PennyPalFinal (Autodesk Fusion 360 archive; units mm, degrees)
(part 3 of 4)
extrude "Extrude211" add of existing geometry blind 2.8
sketch "Sketch51" plane through (0, 0, -35) normal (0, 0, -1) x axis (1, 0, 0)
  line L1 (35, 10.0895) -> (24, 10.0895)
  line L2 (35, 24.0895) -> (35, 10.0895)
  line L3 (24, 24.0895) -> (35, 24.0895)
  line L4 (24, 10.0895) -> (24, 24.0895)
  line L5 (37, 8.0895) -> (22, 8.0895)
  line L6 (37, 26.0895) -> (37, 8.0895)
  line L7 (22, 26.0895) -> (37, 26.0895)
  line L8 (22, 8.0895) -> (22, 26.0895)
  line L9 (-24, 24.0895) -> (-35, 24.0895)
  line L10 (-24, 10.0895) -> (-35, 10.0895)
  line L11 (-24, 24.0895) -> (-24, 10.0895)
  line L12 (-35, 24.0895) -> (-24, 24.0895)
  line L13 (-35, 10.0895) -> (-35, 24.0895)
  line L14 (-22, 26.0895) -> (-37, 26.0895)
  line L15 (-22, 26.0895) -> (-22, 8.0895)
  line L16 (-22, 8.0895) -> (-37, 8.0895)
  line L17 (-37, 8.0895) -> (-37, 26.0895)
  dimension "d829" = 2
  dimension "d830" = 2
extrude "Extrude212" add sketch "Sketch51" profile of L1 L2 L3 L4 L7 L6 L8 L5 to an object
extrude "Extrude213" add sketch "Sketch51" profile of L9 L10 L11 L12 L13 L17 L15 L16 L14 to an object
extrude "Extrude214" cut sketch "Sketch51" profile of L1 L2 L3 L4 L9 L10 L11 L12 L13 against normal blind 1
offset_faces "OffsetFaces15" distance -0.2
extrude "Extrude11" cut sketch "speakerchamber" profile of C3 against normal blind 13
offset_faces "OffsetFaces1" distance -1
offset_faces "OffsetFaces2" distance 1
offset_faces "OffsetFaces16" distance -0.2
remove_body "RemoveBody34"
remove_instance "RemoveInstance1"
combine "Combine15"
extrude "Extrude215" add of existing geometry blind 1 bodies "solwall"
extrude "Extrude216" cut of existing geometry to an object
combine "Combine18"
offset_faces "OffsetFaces18" distance -0.7
extrude "Extrude3" add of existing geometry to an object
offset_faces "OffsetFaces21" distance 0.1
offset_faces "OffsetFaces22" distance -0.05
offset_faces "OffsetFaces23" distance -0.05
offset_faces "OffsetFaces24" distance -0.6
offset_faces "OffsetFaces25" distance -0.05
offset_faces "OffsetFaces26" distance -0.1
offset_faces "OffsetFaces27" distance -0.1
offset_faces "OffsetFaces29" distance -0.7
extrude "Extrude217" add of existing geometry to an object
offset_faces "OffsetFaces31" distance -0.2
sketch "Sketch52" plane through (0, 0, -55) normal (0, 0, -1) x axis (1, 0, 0)
  line L1 (-17.5, -30.7246) -> (17.5, -30.7246)
  line L2 (17.5, 30.7246) -> (-17.5, 30.7246)
  line L3 (36.3634, -30.4187) -> (34.0742, -30.4187)
  line L4 (37.5634, -30.4187) -> (36.3634, -30.4187)
  line L5 (37.5634, -39.466) -> (37.5634, -30.4187)
  line L6 (36.3634, -39.466) -> (37.5634, -39.466)
  line L7 (27.3808, -39.466) -> (36.3634, -39.466)
  line L8 (26.1808, -39.466) -> (27.3808, -39.466)
  line L9 (26.1808, -33.5357) -> (26.1808, -39.466)
  curve K1 (-20.8113, 34.4824) -> (-27.9104, 39.7996)
  curve K2 (-48.969, 26.4968) -> (-47.2168, 17.802)
  curve K3 (-47.2168, -17.802) -> (-48.969, -26.4968)
  curve K4 (-27.9104, -39.7996) -> (-20.8113, -34.4824)
  line L10 (15.2717, -34.641) -> (-17.5, -34.641)
  curve K5 (15.2717, -34.641) -> (21.515, -40.142)
  curve K6 (43.6144, -30.7496) -> (44.3437, -21.8956)
  curve K7 (44.3437, 21.8956) -> (43.6144, 30.7496)
  curve K8 (21.515, 40.142) -> (15.2717, 34.641)
  line L11 (-17.5, 34.641) -> (15.2717, 34.641)
  line L12 (0, 30) -> (0, -30.7246)
  line L13 (17.5, 28.7246) -> (-17.5, 28.7246)
  line L14 (-17.5, -28.7246) -> (17.5, -28.7246)
  line L15 (-17.5, 30.7246) -> (-17.5, -30.7246)
  line L16 (17.5, 30.7246) -> (17.5, -30.7246)
  arc A1 centre (31.8067, -32.1137) radius 11.1166 clockwise from (20.9426, -34.4695) to (20.801, -30.5467)
  arc A2 centre (17.5, 0) radius 30.7246 clockwise from (20.801, -30.5467) to (17.5, -30.7246)
  arc A3 centre (-17.5, 0) radius 30.7246 clockwise from (-17.5, -30.7246) to (-17.5, 30.7246)
  arc A4 centre (17.5, 0) radius 30.7246 clockwise from (17.5, 30.7246) to (36.7751, -23.9263)
  arc A5 centre (34.2917, -30.336) radius 6.8739 clockwise from (36.7751, -23.9263) to (39.9277, -26.4007)
  arc A6 centre (17.5, 0) radius 34.641 clockwise from (39.9277, -26.4007) to (34.0742, -30.4187)
  arc A7 centre (17.5, 0) radius 34.641 clockwise from (26.1808, -33.5357) to (20.9426, -34.4695)
  arc A8 centre (-17.5, 0) radius 34.641 clockwise from (-20.8113, 34.4824) to (-17.5, 34.641)
  arc A9 centre (-37.8687, 32.2443) radius 12.5 clockwise from (-48.969, 26.4968) to (-27.9104, 39.7996)
  arc A10 centre (-17.5, 0) radius 34.641 clockwise from (-47.2168, -17.802) to (-47.2168, 17.802)
  arc A11 centre (-37.8687, -32.2443) radius 12.5 clockwise from (-27.9104, -39.7996) to (-48.969, -26.4968)
  arc A12 centre (-17.5, 0) radius 34.641 clockwise from (-17.5, -34.641) to (-20.8113, -34.4824)
  arc A13 centre (31.2041, -32.2443) radius 12.5 clockwise from (43.6144, -30.7496) to (21.515, -40.142)
  arc A14 centre (17.5, 0) radius 34.641 clockwise from (44.3437, 21.8956) to (44.3437, -21.8956)
  arc A15 centre (31.2041, 32.2443) radius 12.5 clockwise from (21.515, 40.142) to (43.6144, 30.7496)
  arc A16 centre (-37.8687, -32.2443) radius 10.5 clockwise from (-27.4117, -33.1928) to (-43.217, -23.2085)
  arc A17 centre (-17.5, 0) radius 34.641 clockwise from (-27.4117, -33.1928) to (-43.217, -23.2085)
  arc A18 centre (31.2041, 32.2443) radius 10.5 clockwise from (20.9426, 34.4695) to (39.9277, 26.4007)
  arc A19 centre (17.5, 0) radius 34.641 clockwise from (20.9426, 34.4695) to (39.9277, 26.4007)
  arc A20 centre (-37.8687, 32.2443) radius 10.5 clockwise from (-43.217, 23.2085) to (-27.4117, 33.1928)
  arc A21 centre (-17.5, 0) radius 34.641 clockwise from (-43.217, 23.2085) to (-27.4117, 33.1928)
  arc A22 centre (17.5, 0) radius 30.7246 clockwise from (17.5, 30.7246) to (17.5, -30.7246)
  arc A23 centre (17.5, 0) radius 28.7246 clockwise from (17.5, 28.7246) to (35.5204, -22.3689)
  arc A24 centre (-17.5, 0) radius 28.7246 clockwise from (-17.5, -28.7246) to (-17.5, 28.7246)
  arc A25 centre (17.5, 0) radius 28.7246 clockwise from (20.5862, -28.5583) to (17.5, -28.7246)
  arc A26 centre (17.5, 0) radius 28.7246 clockwise from (17.5, 28.7246) to (17.5, -28.7246)
  point P50 (0, -30.7246)
  point P7 (-17.5, -30.7246)
  point P54 (17.5, -30.7246)
  point P8 (-17.5, 30.7246)
  point P53 (17.5, 30.7246)
  midpoint L1 P50
  perpendicular L2 L12
  symmetric P7 L12 P54
  symmetric P8 L12 P53
  symmetric A3 L12 A22
  dimension "d866" = -2
  dimension "d867" = -2
extrude "Extrude218" add sketch "Sketch52" profile of A2 L1 A3 L2 A4 A22 A25 A24 L13 L14 A23 A26 against normal blind 2
extrude "Extrude219" add sketch "Sketch52" profile of A3 A24 L15 to an object
extrude "Extrude220" add sketch "Sketch52" profile of A2 A4 A22 A25 A23 A26 L16 to an object
extrude "Extrude221" add sketch "Sketch52" profile of L1 L2 L13 L14 L15 L16 along normal blind 2
offset_faces "OffsetFaces33" distance -0.6
fillet "Fillet30" radius 2
fillet "Fillet31" radius 3
fillet "Fillet32" radius 2
sketch "Sketch54" plane through (80.6339, 0, 0) normal (-1, 0, 0) x axis (0, -1, 0)
  line L1 (2.5561, -23.9) -> (-2.4939, -23.9)
  line L2 (-2.4939, 23.57) -> (2.5561, 23.57)
  line L3 (-26.2289, -0.165) -> (26.2911, -0.165)
  line L4 (0.0311, 23.57) -> (0.0311, -23.9)
  circle C1 centre (24.2711, -0.165) radius 1.0605
  circle C2 centre (-24.2089, -0.165) radius 1.0605
  circle C3 centre (0.0311, -0.165) radius 17.675
  arc A1 centre (2.5561, -0.165) radius 23.735 clockwise from (2.5561, 23.57) to (2.5561, -23.9)
  arc A2 centre (-2.4939, -0.165) radius 23.735 clockwise from (-2.4939, -23.9) to (-2.4939, 23.57)
  point P11 (26.2911, -0.165)
  point P12 (-26.2289, -0.165)
  point P13 (0.0311, -23.9)
  point P14 (0.0311, 23.57)
  midpoint A1 P11
  midpoint A2 P12
  midpoint L1 P13
  midpoint L2 P14
offset_faces "OffsetFaces34" distance -0.2
sketch "Sketch55" plane through (0, 0, -66) normal (0, 0, -1) x axis (1, 0, 0)
  curve K1 (34.0494, -20.0725) -> (20.4661, -25.8455)
  curve K2 (-27.4384, -25.3554) -> (-36.128, -19.8661)
  curve K3 (-36.128, 19.8661) -> (-27.4384, 25.3554)
  curve K4 (20.4661, 25.8455) -> (34.0494, 20.0725)
  arc A1 centre (31.2041, -32.2443) radius 12.5 clockwise from (34.0494, -20.0725) to (20.4661, -25.8455)
  arc A2 centre (-37.8687, -32.2443) radius 12.5 clockwise from (-27.4384, -25.3554) to (-36.128, -19.8661)
  arc A3 centre (-37.8687, 32.2443) radius 12.5 clockwise from (-36.128, 19.8661) to (-27.4384, 25.3554)
  arc A4 centre (31.2041, 32.2443) radius 12.5 clockwise from (20.4661, 25.8455) to (34.0494, 20.0725)
  circle C1 centre (31.2041, -32.2443) radius 10.05
  circle C2 centre (-37.8687, -32.2443) radius 10.05
  circle C3 centre (-37.8687, 32.2443) radius 10.05
  circle C4 centre (31.2041, 32.2443) radius 10.05
  concentric A1 C1
  concentric A2 C2
  concentric A3 C3
  concentric A4 C4
  dimension "d888" diameter C1 = 20.1
  dimension "d889" diameter C2 = 20.1
  dimension "d890" diameter C3 = 20.1
  dimension "d891" diameter C4 = 20.1
extrude "Extrude222" cut sketch "Sketch55" profile of C1 C2 C3 C4 against normal blind 1
chamfer "Chamfer1" distance 2
sketch "Sketch57" plane through (0, 0, -55) normal (0, 0, -1) x axis (1, 0, 0)
  line L1 (-17.5, -30.7246) -> (17.5, -30.7246)
  line L2 (17.5, 30.7246) -> (-17.5, 30.7246)
  line L3 (36.3634, -30.4187) -> (34.0742, -30.4187)
  line L4 (37.5634, -30.4187) -> (36.3634, -30.4187)
  line L5 (37.5634, -39.466) -> (37.5634, -30.4187)
  line L6 (36.3634, -39.466) -> (37.5634, -39.466)
  line L7 (27.3808, -39.466) -> (36.3634, -39.466)
  line L8 (26.1808, -39.466) -> (27.3808, -39.466)
  line L9 (26.1808, -33.5357) -> (26.1808, -39.466)
  curve K1 (-20.8113, 34.4824) -> (-27.9104, 39.7996)
  curve K2 (-48.969, 26.4968) -> (-47.2168, 17.802)
  curve K3 (-47.2168, -17.802) -> (-48.969, -26.4968)
  curve K4 (-27.9104, -39.7996) -> (-20.8113, -34.4824)
  line L10 (15.2717, -34.641) -> (-17.5, -34.641)
  curve K5 (15.2717, -34.641) -> (21.515, -40.142)
  curve K6 (43.6144, -30.7496) -> (44.3437, -21.8956)
  curve K7 (44.3437, 21.8956) -> (43.6144, 30.7496)
  curve K8 (21.515, 40.142) -> (15.2717, 34.641)
  line L11 (-17.5, 34.641) -> (15.2717, 34.641)
  line L12 (38, -31) -> (37.5634, -31.0937)
  line L13 (27.5847, -38.0621) -> (36.1595, -38.0621)
  line L14 (27.5847, -33.8783) -> (27.5847, -38.0621)
  line L15 (36.1595, -31.8226) -> (27.5847, -33.8783)
  line L16 (36.1595, -31.8226) -> (36.1595, -38.0621)
  arc A1 centre (31.8067, -32.1137) radius 11.1166 clockwise from (20.9426, -34.4695) to (20.801, -30.5467)
  arc A2 centre (17.5, 0) radius 30.7246 clockwise from (20.801, -30.5467) to (17.5, -30.7246)
  arc A3 centre (-17.5, 0) radius 30.7246 clockwise from (-17.5, -30.7246) to (-17.5, 30.7246)
  arc A4 centre (17.5, 0) radius 30.7246 clockwise from (17.5, 30.7246) to (36.7751, -23.9263)
  arc A5 centre (34.2917, -30.336) radius 6.8739 clockwise from (36.7751, -23.9263) to (39.9277, -26.4007)
  arc A6 centre (17.5, 0) radius 34.641 clockwise from (39.9277, -26.4007) to (34.0742, -30.4187)
  arc A7 centre (17.5, 0) radius 34.641 clockwise from (26.1808, -33.5357) to (20.9426, -34.4695)
  arc A8 centre (-17.5, 0) radius 34.641 clockwise from (-20.8113, 34.4824) to (-17.5, 34.641)
  arc A9 centre (-37.8687, 32.2443) radius 12.5 clockwise from (-48.969, 26.4968) to (-27.9104, 39.7996)
  arc A10 centre (-17.5, 0) radius 34.641 clockwise from (-47.2168, -17.802) to (-47.2168, 17.802)
  arc A11 centre (-37.8687, -32.2443) radius 12.5 clockwise from (-27.9104, -39.7996) to (-48.969, -26.4968)
  arc A12 centre (-17.5, 0) radius 34.641 clockwise from (-17.5, -34.641) to (-20.8113, -34.4824)
  arc A13 centre (31.2041, -32.2443) radius 12.5 clockwise from (43.6144, -30.7496) to (21.515, -40.142)
  arc A14 centre (17.5, 0) radius 34.641 clockwise from (44.3437, 21.8956) to (44.3437, -21.8956)
  arc A15 centre (31.2041, 32.2443) radius 12.5 clockwise from (21.515, 40.142) to (43.6144, 30.7496)
  arc A16 centre (-37.8687, -32.2443) radius 10.5 clockwise from (-27.4117, -33.1928) to (-43.217, -23.2085)
  arc A17 centre (-17.5, 0) radius 34.641 clockwise from (-27.4117, -33.1928) to (-43.217, -23.2085)
  arc A18 centre (31.2041, 32.2443) radius 10.5 clockwise from (20.9426, 34.4695) to (39.9277, 26.4007)
  arc A19 centre (17.5, 0) radius 34.641 clockwise from (20.9426, 34.4695) to (39.9277, 26.4007)
  arc A20 centre (-37.8687, 32.2443) radius 10.5 clockwise from (-43.217, 23.2085) to (-27.4117, 33.1928)
  arc A21 centre (-17.5, 0) radius 34.641 clockwise from (-43.217, 23.2085) to (-27.4117, 33.1928)
  point P53 (37.5634, -31.0937)
  coincident L5 P53
  perpendicular L13 L16
extrude "Extrude224" new body sketch "Sketch57" profile of L14 L13 L15 L16 against normal blind 16
sketch "Sketch58" plane through (65.9971, 0, 46.2117) normal (0.8192, 0, 0.5736) x axis (0, 1, 0)
  curve K1 (-15, -13.837) -> (-15, -13.837)
  curve K2 (15, -13.837) -> (15, -13.837)
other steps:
derived_base_feature "Derived Base Feature1"
derived_base_feature "Derived Base Feature1"
derived_base_feature "Derived Base Feature1"
derived_base_feature "Derived Base Feature1"
derived_base_feature "Derived Base Feature1"
derived_base_feature "piggysketch"
derived_base_feature "Derived Base Feature1"
derived_base_feature "piggysketch"
derived_base_feature "piggysketch"
derived_base_feature "Derived Base Feature1"
derived_base_feature "Sketch3"
derived_base_feature "Derived Base Feature1" bodies "top"
derived_base_feature "piggysketch" bodies "speaker"
derived_base_feature "Derived Base Feature1"
extrude "Extrude1" cut of existing geometry blind -6.5
derived_base_feature "Derived Base Feature1" bodies "bottom"
derived_base_feature "Derived Base Feature1"
base_feature "Base Feature1" bodies "battery"
derived_base_feature "Derived Base Feature1"
derived_base_feature "Derived Base Feature1"
derived_base_feature "Derived Base Feature1"
derived_base_feature "Derived Base Feature1"
derived_base_feature "Derived Base Feature1"
derived_base_feature "Derived Base Feature1"
derived_base_feature "Derived Base Feature1"
derived_base_feature "Derived Base Feature1"
derived_base_feature "Derived Base Feature1"
derived_base_feature "Derived Base Feature1"
derived_base_feature "Derived Base Feature1"
derived_base_feature "Derived Base Feature1"
derived_base_feature "Derived Base Feature1"
derived_base_feature "Derived Base Feature1"
derived_base_feature "Derived Base Feature1"
derived_base_feature "Derived Base Feature1"
derived_base_feature "Derived Base Feature1"
derived_base_feature "Sketch1"
derived_base_feature "Derived Base Feature1"
extrude "Extrude3" add sketch "speakerchamber" profile of A1 A2 A3 A4 L6 L7 against normal blind 3
base_feature "Base Feature2"
base_feature "Base Feature3"
create_component "CreateComponent1"
create_component "CreateComponent2"
create_component "CreateComponent3"
create_component "CreateComponent4"
create_component "CreateComponent5"
create_component "CreateComponent6"
create_component "CreateComponent7"
create_component "CreateComponent8"
create_component "CreateComponent9"
create_component "CreateComponent10"
create_component "CreateComponent11"
create_component "CreateComponent12"
create_component "CreateComponent13"
create_component "CreateComponent14"
create_component "CreateComponent15"
create_component "CreateComponent16"
create_component "CreateComponent17"
create_component "CreateComponent18"
create_component "CreateComponent19"
create_component "CreateComponent20"
create_component "CreateComponent21"
create_component "CreateComponent22"
create_component "CreateComponent23"
create_component "CreateComponent1"
create_component "CreateComponent1"
create_component "CreateComponent2"
create_component "CreateComponent3"
create_component "CreateComponent4"
create_component "CreateComponent1"
create_component "CreateComponent2"
create_component "CreateComponent3"
create_component "CreateComponent4"
create_component "CreateComponent1"
create_component "CreateComponent2"
create_component "CreateComponent3"
create_component "CreateComponent4"
create_component "CreateComponent5"
create_component "CreateComponent6"
create_component "CreateComponent7"
create_component "CreateComponent8"
create_component "CreateComponent9"
create_component "CreateComponent10"
create_component "CreateComponent11"
create_component "CreateComponent12"
create_component "CreateComponent13"
create_component "CreateComponent2"
create_component "CreateComponent1"
create_component "CreateComponent2"
create_component "CreateComponent3"
create_component "CreateComponent3"
create_component "CreateComponent4"
create_component "CreateComponent1"
create_component "CreateComponent2"
create_component "CreateComponent5"
create_component "CreateComponent1"
create_component "CreateComponent2"
create_component "CreateComponent6"
create_component "CreateComponent1"
create_component "CreateComponent2"
create_component "CreateComponent3"
create_component "CreateComponent7"
create_component "CreateComponent1"
create_component "CreateComponent2"
create_component "CreateComponent3"
create_component "CreateComponent4"
create_component "CreateComponent8"
create_component "CreateComponent25"
joint_origin "JointOrigin5"
joint_origin "JointOrigin5"
create_component "CreateComponent26"
create_component "CreateComponent27"
create_component "CreateComponent28"
create_component "CreateComponent29"
create_component "CreateComponent30"
create_component "CreateComponent31"
create_component "CreateComponent32"
reparent_decal "ReparentDecal1"
remove_body "RemoveBody25"
extrude "Extrude1" cut of existing geometry blind -420 second side blind -240
create_component "CreateComponent33"
create_component "CreateComponent34"
create_component "CreateComponent35"
create_component "CreateComponent36"
create_component "CreateComponent47"
create_component "CreateComponent48"
named bodies: "snout", "eyer", "eyel", "leftear", "rightear", "frontleftleg", "frontrightleg", "leftleg", "rightleg", "righteye (1)", "left eye (1)", "tl", "PiggyCompleteShell", "chamber", "battery", "piggy (1)", "Piggyouter", "piggy (1) (2)", "piggy (1) (3)", "speaker", "bottom", "top", "coinplate", "connect", "previous", "piggybottom (2)", "drawer", "drawerfront", "acrylic", "acrbck", "solwall", "neoacr1", "neoacr2", "tail (1)", "Body1 (1)", "Body1 (2)", "Body1 (1) (1)"

design "PCB&CoinChute1"
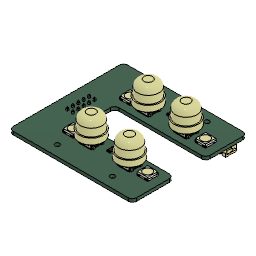
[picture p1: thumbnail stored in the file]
part number: 2026-05-16-19-25-30-712
part number: 2026-05-24-11-27-49-518
description: KiCad electronic assembly
part number: 2026-05-24-18-37-49-600
description: Part Number
part number: 2026-05-24-18-37-49-601
sketch "Sketch1" plane through (0, 0, 0) normal (0, 0, 1) x axis (1, 0, 0)
  line L1 (-17.5, -7.5) -> (17.5, -7.5)
  line L2 (-17.5, 7.5) -> (-17.5, -7.5)
  line L3 (17.5, 7.5) -> (-17.5, 7.5)
  line L4 (17.5, -7.5) -> (17.5, 7.5)
  line L5 (-17.5, 7.5) -> (17.5, -7.5)
  line L6 (17.5, 7.5) -> (-17.5, -7.5)
  line L7 (-14.5, 1.25) -> (14.5, 1.25)
  line L8 (-14.5, -1.25) -> (-14.5, 1.25)
  line L9 (14.5, -1.25) -> (-14.5, -1.25)
  line L10 (14.5, 1.25) -> (14.5, -1.25)
  line L11 (-14.5, -1.25) -> (14.5, 1.25)
  line L12 (14.5, -1.25) -> (-14.5, 1.25)
  line L13 (17.5, -7.5) -> (-17.5, -7.5)
  line L14 (17.5, -14.0997) -> (17.5, -7.5)
  line L15 (-17.5, -14.0997) -> (17.5, -14.0997)
  line L16 (-17.5, -7.5) -> (-17.5, -14.0997)
  point P6 (0, 0)
  point P1 (0, 0)
  point P11 (0, 0)
  point P4 (-17.5, 7.5)
  point P5 (17.5, 7.5)
  point P3 (-17.5, -7.5)
  point P9 (-14.5, -1.25)
  point P10 (14.5, -1.25)
  point P8 (-14.5, 1.25)
  horizontal L1
  perpendicular L1 L2
  parallel L1 L3
  parallel L2 L4
  coincident L5 P6
  coincident L6 P6
  coincident P1 P6
  horizontal L7
  perpendicular L7 L8
  parallel L7 L9
  parallel L8 L10
  coincident L11 P11
  coincident L12 P11
  coincident P6 P11
  horizontal L13
  vertical L14
  horizontal L15
  vertical L16
  dimension "d1" distance P4 P5 = 35
  dimension "d2" distance P3 P4 = 15
  dimension "d3" distance P9 P10 = 29
  dimension "d4" distance P8 P9 = 2.5
extrude "Extrude1" new body sketch "Sketch1" profile of L1 L2 L3 L4 L7 L8 L9 L10 along normal blind 34 (= "20 mm + 9 mm + 5 mm")
sketch "Sketch2" plane through (0, -7.5, 0) normal (0, -1, 0) x axis (1, 0, 0)
  line L1 (17.5, 0) -> (-17.5, 0)
  line L2 (17.5, 34) -> (17.5, 0)
  line L3 (-17.5, 34) -> (17.5, 34)
  line L4 (-17.5, 0) -> (-17.5, 34)
  line L5 (0, 0) -> (0, 34)
  line L6 (-5.06, 8.4) -> (5.06, 8.4)
  line L7 (-5.06, 16.6) -> (-5.06, 8.4)
  line L8 (5.06, 16.6) -> (-5.06, 16.6)
  line L9 (5.06, 8.4) -> (5.06, 16.6)
  line L10 (-5.06, 16.6) -> (5.06, 8.4)
  line L11 (5.06, 16.6) -> (-5.06, 8.4)
  line L12 (-6.56, 18.1) -> (-6.56, 7.4)
  line L13 (6.56, 18.1) -> (-6.56, 18.1)
  line L14 (6.56, 7.4) -> (6.56, 18.1)
  line L15 (6.56, 6.9) -> (-6.56, 6.9)
  line L16 (-6.56, 7.4) -> (-6.56, 6.9)
  line L17 (6.56, 7.4) -> (6.56, 6.9)
  circle C1 centre (0, 12.5) radius 1.475
  circle C2 centre (0, 12.5) radius 3
  point P6 (0, 34)
  point P1 (0, 0)
  point P7 (0, 0)
  point P12 (0, 12.5)
  point P13 (0, 12.5)
  point P14 (0, 12.5)
  point P10 (-5.06, 16.6)
  point P11 (5.06, 16.6)
  point P9 (-5.06, 8.4)
  midpoint L3 P6
  coincident P1 P7
  horizontal L6
  perpendicular L6 L7
  parallel L6 L8
  parallel L7 L9
  coincident L10 P12
  coincident L11 P12
  coincident L5 P12
  coincident P12 P13
  coincident P13 P14
  perpendicular L15 L16
  perpendicular L15 L17
  dimension "d7" distance P10 P11 = 10.12
  dimension "d8" distance P9 P10 = 8.2
  dimension "d9" diameter C1 = 2.95
  dimension "d10" diameter C2 = 6
  dimension "d11" distance L3 P14 = 21.5 (= "20 mm + 1.5 mm")
extrude "Extrude2" cut sketch "Sketch2" profile of C1 against normal blind 8.5
extrude "Extrude3" cut sketch "Sketch2" profile of C1 C2 against normal blind 6.5
extrude "Extrude4" cut sketch "Sketch2" profile of L6 L7 L8 L9 C2 against normal blind 2.5 (magnitude of "-6.5 mm + 4 mm")
extrude "Extrude5" add sketch "Sketch2" profile of L6 L7 L8 L9 L13 L14 L12 along normal blind 11
sketch "Sketch10" plane through (-6.56, 0, 0) normal (-1, 0, 0) x axis (0, -1, 0)
  line L1 (7.5, 6.9) -> (7.5, 18.1)
  line L2 (18.5, 18.1) -> (18.5, 6.9)
  line L3 (7.5, 18.1) -> (18.5, 18.1)
  line L4 (18.5, 6.9) -> (7.5, 6.9)
  circle C1 centre (15.84, 14.6) radius 1
  dimension "d255" diameter C1 = 2
extrude "Extrude13" cut sketch "Sketch10" profile of C1 against normal blind 5
extrude "Extrude11" add of existing geometry blind 1
extrude "Extrude14" cut sketch "Sketch10" profile of C1 along normal blind 10
sketch "Sketch3" plane through (17.5, 0, 0) normal (1, 0, 0) x axis (0, 1, 0)
  line L1 (7.5, 0) -> (-7.5, 0)
  line L2 (7.5, 34) -> (7.5, 0)
  line L3 (-7.5, 34) -> (7.5, 34)
  line L4 (-7.5, 0) -> (-7.5, 34)
  line L5 (0, 0) -> (0, 34)
  line L6 (-6.5, 30.5) -> (6.5, 30.5)
  line L7 (-6.5, 24.5) -> (-6.5, 30.5)
  line L8 (6.5, 24.5) -> (-6.5, 24.5)
  line L9 (6.5, 30.5) -> (6.5, 24.5)
  line L10 (-6.5, 24.5) -> (6.5, 30.5)
  line L11 (6.5, 24.5) -> (-6.5, 30.5)
  line L12 (-2.5, 24.5) -> (2.5, 24.5)
  line L13 (-2.5, 30.5) -> (-2.5, 24.5)
  line L14 (2.5, 30.5) -> (-2.5, 30.5)
  line L15 (2.5, 24.5) -> (2.5, 30.5)
  line L16 (-2.5, 30.5) -> (2.5, 24.5)
  line L17 (2.5, 30.5) -> (-2.5, 24.5)
  line L18 (-7, 31.5) -> (7, 31.5)
  line L19 (-7, 0.5) -> (-7, 31.5)
  line L20 (7, 0.5) -> (-7, 0.5)
  line L21 (7, 31.5) -> (7, 0.5)
  line L22 (-7, 0.5) -> (7, 31.5)
  line L23 (7, 0.5) -> (-7, 31.5)
  line L24 (7.5, 4) -> (-7.5, 4)
  circle C1 centre (0, 6.1) radius 1.15
  point P6 (0, 34)
  point P1 (0, 0)
  point P7 (0, 0)
  point P12 (0, 27.5)
  point P17 (0, 27.5)
  point P22 (0, 16)
  point P23 (0, 6.1)
  point P24 (-7.5, 4)
  point P25 (7.5, 4)
  point P10 (-6.5, 24.5)
  point P11 (6.5, 24.5)
  point P9 (-6.5, 30.5)
  point P15 (-2.5, 30.5)
  point P16 (2.5, 30.5)
  point P14 (-2.5, 24.5)
  point P20 (-7, 0.5)
  point P21 (7, 0.5)
  point P19 (-7, 31.5)
  midpoint L3 P6
  coincident P1 P7
  horizontal L6
  perpendicular L6 L7
  parallel L6 L8
  parallel L7 L9
  coincident L10 P12
  coincident L11 P12
  coincident L5 P12
  horizontal L12
  perpendicular L12 L13
  parallel L12 L14
  parallel L13 L15
  coincident L16 P17
  coincident L17 P17
  coincident P12 P17
  horizontal L18
  perpendicular L18 L19
  parallel L18 L20
  parallel L19 L21
  coincident L22 P22
  coincident L23 P22
  coincident L5 P22
  coincident L5 P23
  coincident L4 P24
  coincident L2 P25
  perpendicular L2 L24
  dimension "d21" distance P10 P11 = 13
  dimension "d22" distance P9 P10 = 6
  dimension "d23" distance P15 P16 = 5
  dimension "d24" distance P14 P15 = 6
  dimension "d25" distance P20 P21 = 14
  dimension "d26" distance P19 P20 = 31
  dimension "d27" distance L6 L18 = 1
  dimension "d28" diameter C1 = 2.3
  dimension "d29" distance L20 P23 = 5.6
  dimension "d30" distance L3 P17 = 6.5 (= "20 mm - 13.5 mm")
  dimension "d31" distance L20 L24 = 3.5
extrude "Extrude6" cut sketch "Sketch3" profile of L6 L7 L8 L9 L12 L13 L14 L15 against normal blind 12.2 (magnitude of "-4.00 mm - 8.2 mm")
extrude "Extrude7" cut sketch "Sketch3" profile of L1 L2 L3 L4 L6 L7 L8 L9 L12 L14 L18 L19 L20 L21 C1 L24 against normal blind 0.6
extrude "Extrude9" cut sketch "Sketch3" profile of C1 against normal blind 3
fillet "Fillet1" radius 1 1
fillet "Fillet2" radius 1
fillet "Fillet3" radius 2
offset_faces "OffsetFaces1" distance -0.1
offset_faces "OffsetFaces2" distance -0.1
offset_faces "OffsetFaces4" distance -0.1
offset_faces "OffsetFaces5" distance -0.6
chamfer "Chamfer1" distance 1
chamfer "Chamfer2" distance 1
sketch "Sketch4" plane through (0, 0, 34) normal (0, 0, 1) x axis (-1, 0, 0)
  line L1 (-16.9, -5.5) -> (-16.9, 5.5)
  line L2 (15.5, -7.5) -> (-14.9, -7.5)
  line L3 (17.5, 5.5) -> (17.5, -5.5)
  line L4 (-14.9, 7.5) -> (15.5, 7.5)
  line L5 (15.5, -7.5) -> (-14.9, -7.5)
  line L6 (17.5, 5.5) -> (17.5, -5.5)
  line L7 (-14.9, 7.5) -> (15.5, 7.5)
  line L8 (-16.9, -5.5) -> (-16.9, 5.5)
  arc A1 centre (-14.9, 5.5) radius 2 clockwise from (-16.9, 5.5) to (-14.9, 7.5)
  arc A2 centre (-14.9, -5.5) radius 2 clockwise from (-14.9, -7.5) to (-16.9, -5.5)
  arc A3 centre (15.5, -5.5) radius 2 clockwise from (17.5, -5.5) to (15.5, -7.5)
  arc A4 centre (15.5, 5.5) radius 2 clockwise from (15.5, 7.5) to (17.5, 5.5)
  arc A5 centre (15.5, -5.5) radius 2 clockwise from (17.5, -5.5) to (15.5, -7.5)
  arc A6 centre (15.5, 5.5) radius 2 clockwise from (15.5, 7.5) to (17.5, 5.5)
  arc A7 centre (-14.9, 5.5) radius 2 clockwise from (-16.9, 5.5) to (-14.9, 7.5)
  arc A8 centre (-14.9, -5.5) radius 2 clockwise from (-14.9, -7.5) to (-16.9, -5.5)
component_from_bodies "Body->Comp1"
base_feature "Base Feature1"
base_feature "Base Feature1"
base_feature "Base Feature1"
base_feature "Base Feature1"
base_feature "Base Feature1"
base_feature "Base Feature1"
base_feature "Base Feature1"
base_feature "Base Feature1"
base_feature "Base Feature1"
base_feature "Base Feature1"
base_feature "Base Feature1"
base_feature "Base Feature1"
base_feature "Base Feature1"
base_feature "Base Feature1"
base_feature "Base Feature1"
base_feature "Base Feature1"
as_built_joint "As-built1"
joint "Assemble" alignAngle 0 alignOffsetX 0 alignOffsetY 0 alignOffsetZ -8
sketch "Sketch8" plane through (0, 0, 34) normal (0, 0, 1) x axis (-1, 0, 0)
  line L1 (-16.9, -5.5) -> (-16.9, 5.5)
  line L2 (15.5, -7.5) -> (-14.9, -7.5)
  line L3 (17.5, 5.5) -> (17.5, -5.5)
  line L4 (-14.9, 7.5) -> (15.5, 7.5)
  line L5 (15.6, 2.35) -> (-15.6, 2.35)
  line L6 (15.6, -2.35) -> (15.6, 2.35)
  line L7 (-15.6, -2.35) -> (15.6, -2.35)
  line L8 (-15.6, 2.35) -> (-15.6, -2.35)
  line L9 (-25, -25) -> (25, 25)
  line L10 (25, -25) -> (-25, 25)
  line L11 (7.668, 13.327) -> (-10.307, 13.377)
  line L12 (7.643, -13.323) -> (-10.107, -13.348)
  line L13 (-0.8195, 8.352) -> (-1.8195, 8.352)
  line L14 (-1.8195, 23.352) -> (-0.8195, 23.352)
  line L15 (-1.8195, 23.352) -> (-1.8195, 8.352)
  line L16 (-0.8195, 23.352) -> (-0.8195, 8.352)
  line L17 (-0.732, -8.3355) -> (-1.732, -8.3355)
  line L18 (-1.732, -23.3355) -> (-0.732, -23.3355)
  line L19 (-1.732, -8.3355) -> (-1.732, -23.3355)
  line L20 (-0.732, -8.3355) -> (-0.732, -23.3355)
  line L21 (-10.307, 13.377) -> (-10.107, -13.348)
  line L22 (7.668, 13.327) -> (7.643, -13.323)
  line L23 (-18.0409, 0.0068) -> (-18, 0)
  line L24 (18.6, -0.5) -> (18.6, 0.5)
  line L25 (-18, -0.5) -> (-18, 0.5)
  line L26 (23.1, 0.5) -> (18.6, 0.5)
  line L27 (23.1, -0.5) -> (23.1, 0.5)
  line L28 (18.6, -0.5) -> (23.1, -0.5)
  line L29 (-17.9586, 0.0069) -> (-18, 0)
  line L30 (-18.0409, 0.0068) -> (-15.6, 0.0092)
  line L31 (-23, 0.5) -> (-18, 0.5)
  line L32 (-23, -0.5) -> (-23, 0.5)
  line L33 (-18, -0.5) -> (-23, -0.5)
  arc A1 centre (-14.9, 5.5) radius 2 clockwise from (-16.9, 5.5) to (-14.9, 7.5)
  arc A2 centre (-14.9, -5.5) radius 2 clockwise from (-14.9, -7.5) to (-16.9, -5.5)
  arc A3 centre (15.5, -5.5) radius 2 clockwise from (17.5, -5.5) to (15.5, -7.5)
  arc A4 centre (15.5, 5.5) radius 2 clockwise from (15.5, 7.5) to (17.5, 5.5)
  circle C1 centre (-10.817, 21.883) radius 1.1
  circle C2 centre (14.964, 21.883) radius 1.1
  circle C3 centre (7.668, 13.327) radius 1.4
  circle C4 centre (-10.307, 13.377) radius 1.4
  circle C5 centre (7.643, -13.323) radius 1.4
  circle C6 centre (-10.107, -13.348) radius 1.4
  circle C7 centre (-10.817, -22.44) radius 1.1
  circle C8 centre (14.964, -22.44) radius 1.1
  circle C9 centre (-10.107, -13.348) radius 5
  circle C10 centre (7.643, -13.323) radius 5
  circle C11 centre (7.668, 13.327) radius 5
  circle C12 centre (-10.307, 13.377) radius 5
  circle C13 centre (14.964, 21.883) radius 2
  circle C14 centre (14.964, 21.883) radius 0.9
  circle C15 centre (-10.817, 21.883) radius 0.9
  circle C16 centre (-10.817, 21.883) radius 2
  circle C17 centre (-10.817, -22.44) radius 0.9
  circle C18 centre (-10.817, -22.44) radius 2
  circle C19 centre (14.964, -22.44) radius 0.9
  circle C20 centre (14.964, -22.44) radius 2
  circle C21 centre (7.668, 13.327) radius 5.25
  circle C22 centre (-10.307, 13.377) radius 5.25
  circle C23 centre (-10.107, -13.348) radius 5.25
  circle C24 centre (7.643, -13.323) radius 5.25
  circle C25 centre (7.643, -13.323) radius 5.7
  circle C26 centre (-10.107, -13.348) radius 5.7
  circle C27 centre (7.668, 13.327) radius 5.7
  circle C28 centre (-10.307, 13.377) radius 5.7
  circle C29 centre (0, 0) radius 30.5287
  circle C30 centre (0, 0) radius 34.1551
  circle C31 centre (0, 0) radius 31.5287
  point P22 (0, 0)
  point P1 (0, 0)
  point P26 (-10.307, 13.377)
  point P51 (-10.307, 13.377)
  point P25 (7.668, 13.327)
  point P52 (7.668, 13.327)
  point P31 (-10.107, -13.348)
  point P53 (-10.107, -13.348)
  point P27 (7.643, -13.323)
  point P54 (7.643, -13.323)
  point P57 (-1.3195, 13.352)
  point P62 (-1.232, -13.3355)
  point P32 (7.643, -13.323)
  point P65 (7.643, -13.323)
  point P33 (7.668, 13.327)
  point P66 (7.668, 13.327)
  point P70 (15.6, 0)
  point P76 (-17.9586, 0.0069)
  point P77 (-15.6, 0.0092)
  point P80 (0, 0)
  point P20 (-25, -25)
  point P21 (25, -25)
  point P19 (-25, 25)
  point P55 (-1.8195, 8.352)
  point P56 (-0.8195, 8.352)
  point P60 (-1.732, -8.3355)
  point P61 (-0.732, -8.3355)
  point P69 (18.6, 0.5)
  point P73 (23.1, 0.5)
  point P74 (23.1, -0.5)
  point P71 (-18, 0.5)
  point P78 (-23, 0.5)
  point P79 (-23, -0.5)
  coincident L9 P22
  coincident L10 P22
  coincident P1 P22
  concentric C6 C9
  concentric C5 C10
  concentric C3 C11
  concentric C4 C12
  concentric C2 C13
  concentric C2 C14
  concentric C1 C15
  concentric C1 C16
  concentric C7 C17
  concentric C7 C18
  concentric C8 C19
  concentric C8 C20
  coincident P26 P51
  coincident P25 P52
  coincident P31 P53
  coincident P27 P54
  midpoint L11 P57
  perpendicular L14 L15
  perpendicular L14 L16
  midpoint L12 P62
  perpendicular L17 L19
  perpendicular L17 L20
  coincident P32 P65
  coincident P33 P66
  midpoint L6 P70
  perpendicular L24 L26
  perpendicular L26 L27
  perpendicular L24 L28
  coincident L30 P76
  coincident L8 P77
  perpendicular L25 L31
  perpendicular L31 L32
  perpendicular L25 L33
  coincident P22 P80
  dimension "d98" distance P20 P21 = 50
  dimension "d99" distance P19 P20 = 50
  dimension "d104" diameter C9 = 10
  dimension "d105" diameter C10 = 10
  dimension "d106" diameter C11 = 10
  dimension "d107" diameter C12 = 10
  dimension "d122" diameter C13 = 4
  dimension "d123" diameter C14 = 1.8
  dimension "d124" diameter C15 = 1.8
  dimension "d125" diameter C16 = 4
  dimension "d126" diameter C17 = 1.8
  dimension "d127" diameter C18 = 4
  dimension "d128" diameter C19 = 1.8
  dimension "d129" diameter C20 = 4
  dimension "d132" = 0.25
  dimension "d133" = 0.25
  dimension "d134" = 0.25
  dimension "d135" = 0.25
  dimension "d141" = 0.7
  dimension "d142" = 0.7
  dimension "d143" = 0.7
  dimension "d144" = 0.7
  dimension "d175" distance P55 P56 = 1
  dimension "d178" distance P60 P61 = 1
  dimension "d186" distance P69 P73 = 4.5
  dimension "d187" distance P73 P74 = 1
  dimension "d188" distance P71 P78 = 5
  dimension "d189" distance P78 P79 = 1
  dimension "d201" = 1
extrude "Extrude5" add sketch "Sketch8" profile of A1 L1 A2 L2 A3 L3 A4 L4 C1 C2 C3 C4 C5 C6 C7 C8 C9 C10 C11 C12 C13 C14 C15 C16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 against normal blind 2
mirror_component "MirrorComponent1"
derived_instance "DerivedInstance1"
sketch "Sketch12" plane through (-5.16, 0, 0) normal (1, 0, 0) x axis (0, 1, 0)
  line L1 (-5, 7.8) -> (-18.5, 7.8)
  line L2 (-5, 17.2) -> (-5, 7.8)
  line L3 (-18.5, 17.2) -> (-5, 17.2)
  line L4 (-18.5, 7.8) -> (-18.5, 17.2)
  circle C1 centre (-15.84, 14.6) radius 1
extrude "Extrude4" add sketch "Sketch8" profile of C3 C4 C5 C6 C9 C10 C11 C12 along normal blind 3
fillet "Fillet2" radius 3
sketch "Sketch9" plane through (0, 0, 32) normal (0, 0, -1) x axis (1, 0, 0)
  line L1 (-15.5, -7.5) -> (14.9, -7.5)
  line L2 (-17.5, 5.5) -> (-17.5, -5.5)
  line L3 (14.9, 7.5) -> (-15.5, 7.5)
  line L4 (16.9, -5.5) -> (16.9, 5.5)
  circle C1 centre (-7.668, 13.327) radius 1.4
  circle C2 centre (10.307, 13.377) radius 1.4
  circle C3 centre (10.107, -13.348) radius 1.4
  circle C4 centre (-7.643, -13.323) radius 1.4
  arc A1 centre (-15.5, -5.5) radius 2 clockwise from (-15.5, -7.5) to (-17.5, -5.5)
  arc A2 centre (-15.5, 5.5) radius 2 clockwise from (-17.5, 5.5) to (-15.5, 7.5)
  arc A3 centre (14.9, 5.5) radius 2 clockwise from (14.9, 7.5) to (16.9, 5.5)
  arc A4 centre (14.9, -5.5) radius 2 clockwise from (16.9, -5.5) to (14.9, -7.5)
  circle C5 centre (-7.668, 13.327) radius 5.7
  circle C6 centre (10.307, 13.377) radius 5.7
  circle C7 centre (-7.643, -13.323) radius 5.7
  circle C8 centre (10.107, -13.348) radius 5.7
  circle C9 centre (0, 0) radius 30.5287
extrude "Extrude7" add sketch "Sketch9" profile of C1 C2 C3 C4 along normal blind 2.8
extrude "Extrude8" cut sketch "Sketch8" profile of C9 C10 C11 C12 C21 C22 C23 C24 against normal blind 2
extrude "Extrude9" cut of existing geometry to an object
extrude "Extrude10" add sketch "Sketch9" profile of C2 along normal blind 1
offset_faces "OffsetFaces1" distance 4.3
extrude "Extrude11" add sketch "Sketch9" profile of C2 along normal blind 2.8
extrude "Extrude12" cut of existing geometry to an object
extrude "Extrude13" add sketch "Sketch9" profile of C1 along normal blind 1
offset_faces "OffsetFaces2" distance 4.3
extrude "Extrude14" add sketch "Sketch9" profile of C1 along normal blind 2.8
extrude "Extrude15" cut of existing geometry to an object
extrude "Extrude16" add sketch "Sketch9" profile of C3 along normal blind 1
offset_faces "OffsetFaces3" distance 4.3
extrude "Extrude17" cut of existing geometry to an object
extrude "Extrude18" add sketch "Sketch9" profile of C4 along normal blind 1
offset_faces "OffsetFaces4" distance 4.3
extrude "Extrude19" add sketch "Sketch9" profile of C4 along normal blind 2.8
extrude "Extrude20" add sketch "Sketch9" profile of C3 along normal blind 2.8
extrude "Extrude21" add sketch "Sketch8" profile of L13 L14 L15 L16 L17 L18 L19 L20 L24 L25 L26 L27 L28 L31 L32 L33 against normal blind 7
extrude "Extrude22" add sketch "Sketch8" profile of C29 C30 against normal blind 2
extrude "Extrude23" add sketch "Sketch8" profile of C29 C30 C31 against normal blind 3
extrude "Extrude24" cut sketch "Sketch8" profile of C29 C30 against normal blind 2
extrude "Extrude31" add sketch "Sketch8" profile of C29 C31 against normal blind 2
extrude "Extrude25" add sketch "Sketch8" profile of C29 C31 against normal blind 2
joint "Assemble" alignAngle 0 alignOffsetX 0 alignOffsetY 0 alignOffsetZ 0
extrude "Extrude26" add of existing geometry to an object
move_face "MoveFace1"
copy_paste_bodies "CopyPasteBodies1"
move "Move1"
offset_faces "OffsetFaces6" distance 0.1
move_face "MoveFace1"
offset_faces "OffsetFaces1" distance -0.1
offset_faces "OffsetFaces2" distance -0.1
offset_faces "OffsetFaces5" distance 0.1
move_face "MoveFace2"
extrude "Extrude30" add sketch "Sketch8" profile of C1 C2 C7 C8 C13 C16 C18 C20 to an object
extrude "Extrude32" add of existing geometry to an object
extrude "Extrude33" cut of existing geometry blind -5.8
extrude "Extrude34" add of existing geometry to an object
extrude "Extrude35" add of existing geometry to an object
sketch "Sketch13" plane through (0, 0, 34) normal (0, 0, 1) x axis (-1, 0, 0)
  dimension "d268" = 5
  dimension "d269" = 0 (= "Text1-Text")
  dimension "d274" = 5
  dimension "d275" = 0 (= "Text3-Text")
  dimension "d278" = 5
  dimension "d279" = 0 (= "Text3-Text")
  dimension "d280" = 5
  dimension "d281" = "10"
extrude "Extrude36" cut sketch "Sketch13" against normal blind 1
component_from_bodies "Body->Comp1"
extrude "Extrude1" new body of existing geometry blind 1
extrude "Extrude2" cut of existing geometry blind -5.5
extrude "Extrude3" cut of existing geometry blind -0.4
extrude "Extrude4" add of existing geometry blind 8.32
extrude "Extrude5" add of existing geometry blind 2.42
offset_faces "OffsetFaces1" distance 1
offset_faces "OffsetFaces2" distance -0.3
offset_faces "OffsetFaces4" distance -1
move_face "MoveFace3"
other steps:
base_feature "Base Feature1"
base_feature "Base Feature1"
derived_base_feature "Derived Base Feature"
base_feature "Base Feature1"
create_component "CreateComponent2"
reparent_decal "ReparentDecal1"
remove_body "RemoveBody1"
create_component "CreateComponent1"
create_component "CreateComponent1"
create_component "CreateComponent2"
create_component "CreateComponent3"
create_component "CreateComponent4"
create_component "CreateComponent2"
create_component "CreateComponent3"
create_component "CreateComponent1"
create_component "CreateComponent2"
create_component "CreateComponent1"
create_component "CreateComponent2"
create_component "CreateComponent3"
create_component "CreateComponent4"
create_component "CreateComponent3"
create_component "CreateComponent4"
create_component "CreateComponent4"
create_component "CreateComponent5"
create_component "CreateComponent6"
create_component "CreateComponent7"
create_component "CreateComponent5"
joint_origin "JointOrigin2"
joint_origin "JointOrigin8"
create_component "CreateComponent6"
joint_origin "JointOrigin1"
joint_origin "JointOrigin9"
create_component "CreateComponent1"
reparent_decal "ReparentDecal1"
remove_body "RemoveBody1"

design "boost"
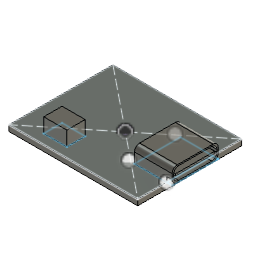
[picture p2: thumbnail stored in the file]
part number: 2026-06-03-11-04-21-634
sketch "Sketch1" plane through (0, 0, 0) normal (0, 0, 1) x axis (1, 0, 0)
  line L1 (-12.55, 10.13) -> (12.55, 10.13)
  line L2 (-12.55, -10.13) -> (-12.55, 10.13)
  line L3 (12.55, -10.13) -> (-12.55, -10.13)
  line L4 (12.55, 10.13) -> (12.55, -10.13)
  line L5 (-12.55, -10.13) -> (12.55, 10.13)
  line L6 (12.55, -10.13) -> (-12.55, 10.13)
  line L7 (12.55, 4.48) -> (12.55, -4.48)
  line L8 (5.3395, 4.3099) -> (5.2, 4.48)
  line L9 (13.62, 4.48) -> (13.62, -4.48)
  line L10 (13.62, 4.48) -> (6.27, 4.48)
  line L11 (5.2, -4.48) -> (5.3395, -4.3099)
  line L12 (13.62, -4.48) -> (6.27, -4.48)
  line L13 (6.27, -4.48) -> (6.27, 4.48)
  line L14 (-3.1632, -8.2117) -> (-7.6611, -8.2117)
  line L15 (-3.1632, -4.6419) -> (-3.1632, -8.2117)
  line L16 (-7.6611, -4.6419) -> (-3.1632, -4.6419)
  line L17 (-7.6611, -8.2117) -> (-7.6611, -4.6419)
  point P6 (0, 0)
  point P1 (0, 0)
  point P7 (12.55, 4.48)
  point P15 (5.3395, -4.3099)
  point P16 (5.3395, 4.3099)
  point P4 (-12.55, -10.13)
  point P5 (12.55, -10.13)
  point P3 (-12.55, 10.13)
  point P13 (6.27, -4.48)
  point P14 (6.27, 4.48)
  point P11 (13.62, 4.48)
  horizontal L1
  perpendicular L1 L2
  parallel L1 L3
  parallel L2 L4
  coincident L5 P6
  coincident L6 P6
  coincident P1 P6
  coincident L4 P7
  perpendicular L9 L10
  perpendicular L9 L12
  coincident L6 P15
  coincident L5 P16
  perpendicular L12 L13
  horizontal L14
  vertical L15
  horizontal L16
  vertical L17
  dimension "d1" distance P4 P5 = 25.1
  dimension "d2" distance P3 P4 = 20.26
  dimension "d8" distance P13 P14 = 8.96
  dimension "d9" distance P11 P14 = 7.35
extrude "Extrude1" new body sketch "Sketch1" profile of L1 L2 L3 L4 L7 L10 L12 L13 L14 L15 L16 L17 against normal blind 1.15
extrude "Extrude2" add sketch "Sketch1" profile of L14 L15 L16 L17 along normal blind 2.82
extrude "Extrude3" add sketch "Sketch1" profile of L4 L7 L9 L10 L12 L13 along normal blind 3
sketch "Sketch2" plane through (13.62, 0, 0) normal (1, 0, 0) x axis (0, 1, 0)
  line L1 (4.48, 0) -> (-4.48, 0)
  line L2 (4.48, 3) -> (4.48, 0)
  line L3 (-4.48, 3) -> (4.48, 3)
  line L4 (-4.48, 0) -> (-4.48, 3)
  line L5 (4.2237, 0.2563) -> (-4.2237, 0.2563)
  line L6 (4.2237, 2.7437) -> (4.2237, 0.2563)
  line L7 (-4.2237, 2.7437) -> (4.2237, 2.7437)
  line L8 (-4.2237, 0.2563) -> (-4.2237, 2.7437)
  line L9 (-3.8199, 1.2477) -> (3.7847, 1.2477)
  line L10 (-3.8199, 1.6479) -> (-3.8199, 1.2477)
  line L11 (3.7847, 1.6479) -> (-3.8199, 1.6479)
  line L12 (3.7847, 1.2477) -> (3.7847, 1.6479)
  line L13 (-3.8199, 1.6479) -> (3.7847, 1.2477)
  line L14 (3.7847, 1.6479) -> (-3.8199, 1.2477)
  point P14 (-0.0176, 1.4478)
  horizontal L9
  perpendicular L9 L10
  parallel L9 L11
  parallel L10 L12
  coincident L13 P14
  coincident L14 P14
  dimension "d16" = -0.2563
extrude "Extrude4" cut sketch "Sketch2" profile of L8 L7 L6 L5 L9 L10 L11 L12 against normal blind 7
fillet "Fillet1" radius 1
fillet "Fillet2" radius 1
fillet "Fillet3" radius 1
fillet "Fillet4" radius 1
fillet "Fillet5" radius 1

design "annular-snap-speaker1"
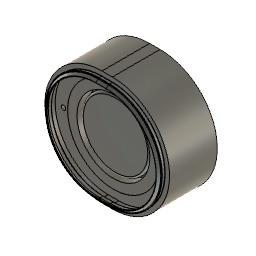
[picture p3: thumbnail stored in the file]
part number: 2026-05-30-15-56-48-698
part number: 2026-05-31-18-06-01-991
part number: 2026-05-31-18-06-02-000
part number: 2026-05-31-20-52-18-462
part number: 2026-05-31-22-14-57-015
sketch "Sketch1" plane through (0, 0, 0) normal (0, 1, 0) x axis (1, 0, 0)
  line L1 (-22, 22) -> (22, -22)
  line L2 (-15.2028, -15.2028) -> (-22, -22)
  line L3 (22, 22) -> (-12.3744, -12.3744)
  line L4 (0, 22) -> (0, -22)
  line L5 (22, 0) -> (-22, 0)
  line L6 (-16.5, -26) -> (16.5, -26)
  line L7 (26, -16.5) -> (26, 16.5)
  line L8 (16.5, 26) -> (-16.5, 26)
  line L9 (-26, 16.5) -> (-26, -16.5)
  circle C1 centre (0, 0) radius 16.5
  circle C2 centre (0, 0) radius 17.5
  circle C3 centre (0, 0) radius 22
  arc A1 centre (-16.5, -16.5) radius 9.5 clockwise from (-16.5, -26) to (-26, -16.5)
  arc A2 centre (16.5, -16.5) radius 9.5 clockwise from (26, -16.5) to (16.5, -26)
  arc A3 centre (16.5, 16.5) radius 9.5 clockwise from (16.5, 26) to (26, 16.5)
  arc A4 centre (-16.5, 16.5) radius 9.5 clockwise from (-26, 16.5) to (-16.5, 26)
  point P1 (0, 0)
  point P2 (0, 0)
  point P8 (0, 0)
  point P10 (-12.3744, -12.3744)
  point P15 (0, 0)
  point P6 (-22, 22)
  point P7 (22, 22)
  point P5 (-22, -22)
  coincident P1 P2
  coincident L1 P8
  coincident P8 L3
  coincident P1 P8
  coincident C2 P10
  collinear L2 L3
  coincident P8 P15
  dimension "d3" diameter C1 = 33
  dimension "d7" = 1
  dimension "d31" distance P6 P7 = 44
  dimension "d32" distance P5 P6 = 44
  dimension "d121" diameter C3 = 44
extrude "Extrude1" new body sketch "Sketch1" profile of C1 along normal blind 6 bodies "speaker"
extrude "Extrude2" new body sketch "Sketch1" profile of C1 C2 along normal blind 6
extrude "Extrude3" cut sketch "Sketch1" profile of C1 C2 along normal blind 5
extrude "Extrude4" cut sketch "Sketch1" profile of C1 along normal blind 1
sketch "Sketch2" plane through (0, 6, 0) normal (0, 1, 0) x axis (-1, 0, 0)
  circle C1 centre (0, 0) radius 11.9
  circle C2 centre (0, 0) radius 17.5
  circle C3 centre (0, 0) radius 15
  circle C4 centre (0, 0) radius 22
  point P1 (0, 0)
  point P2 (0, 0)
  point P3 (0, 0)
  coincident P1 P2
  coincident P1 P3
  concentric C1 C3
  dimension "d14" diameter C1 = 23.8
  dimension "d15" diameter C2 = 35
  dimension "d16" diameter C3 = 30
extrude "Extrude5" add sketch "Sketch2" profile of C2 C3 along normal blind 2
extrude "Extrude6" add sketch "Sketch2" profile of C1 C3 along normal blind 4
extrude "Extrude7" add sketch "Sketch2" profile of C1 along normal blind 8
fillet "Fillet1" radius 2.5
fillet "Fillet2" radius 2
fillet "Fillet4" radius 1
extrude "Extrude9" new body sketch "Sketch1" along normal blind 2
move "Move2"
sketch "Sketch3" plane through (0, 0, 0) normal (0, 1, 0) x axis (1, 0, 0)
  line L1 (-2.5, 27.5) -> (2.5, 27.5)
  line L2 (-30, -27.5) -> (-30, 27.5)
  line L3 (2.5, -27.5) -> (-2.5, -27.5)
  line L4 (30, 27.5) -> (30, -27.5)
  line L5 (-30, -27.5) -> (30, 27.5)
  line L6 (30, -27.5) -> (-30, 27.5)
  line L7 (30, 0) -> (-30, 0)
  line L8 (0, 27.5) -> (0, -27.5)
  line L9 (30, 27.5) -> (-30, 27.5)
  line L10 (30, -27.5) -> (-30, -27.5)
  line L11 (2.5, -25.5) -> (-2.5, -25.5)
  line L12 (-2.5, 25.5) -> (2.5, 25.5)
  line L13 (0, -27.5) -> (0, 27.5)
  line L14 (-2.5, 24) -> (2.5, 24)
  line L15 (2.5, -24) -> (-2.5, -24)
  line L16 (-2.5, 23.5) -> (2.5, 23.5)
  line L17 (2.5, -23.5) -> (-2.5, -23.5)
  arc A1 centre (-2.5, 0) radius 27.5 clockwise from (-2.5, -27.5) to (-2.5, 27.5)
  arc A2 centre (2.5, 0) radius 27.5 clockwise from (2.5, 27.5) to (2.5, -27.5)
  arc A3 centre (-2.5, 0) radius 25.5 clockwise from (-2.5, -25.5) to (-2.5, 25.5)
  arc A4 centre (2.5, 0) radius 25.5 clockwise from (2.5, 25.5) to (2.5, -25.5)
  circle C1 centre (0, 0) radius 17.5
  arc A5 centre (2.5, 0) radius 24 clockwise from (2.5, 24) to (2.5, -24)
  arc A6 centre (2.5, 0) radius 23.5 clockwise from (2.5, 23.5) to (2.5, -23.5)
  arc A7 centre (-2.5, 0) radius 23.5 clockwise from (-2.5, -23.5) to (-2.5, 23.5)
  circle C2 centre (0, 0) radius 22
  circle C3 centre (24, 0) radius 1.05
  circle C4 centre (-24, 0) radius 1.05
  point P6 (0, 0)
  point P1 (0, 0)
  point P7 (-30, 0)
  point P8 (30, 0)
  point P9 (0, -27.5)
  point P10 (0, 27.5)
  point P4 (-30, -27.5)
  point P5 (30, -27.5)
  point P3 (-30, 27.5)
  horizontal L1
  perpendicular L1 L2
  parallel L1 L3
  parallel L2 L4
  coincident L5 P6
  coincident L6 P6
  coincident P1 P6
  midpoint L2 P7
  midpoint L4 P8
  coincident P7 A1
  coincident P8 A2
  coincident L3 P9
  coincident L1 P10
  perpendicular L4 L9
  perpendicular L4 L10
  perpendicular L3 L13
  symmetric L13 C3 C4
  dimension "d41" distance P4 P5 = 60
  dimension "d42" distance P3 P4 = 55
  dimension "d43" diameter A1 = 55
  dimension "d45" = -2
  dimension "d106" = -1.5
  dimension "d107" = -2
  dimension "d135" diameter C3 = 2.1
extrude "Extrude10" new body sketch "Sketch3" profile of L1 L3 A1 A2 A4 L11 L12 A3 along normal blind 20 bodies "bottom"
extrude "Extrude11" cut sketch "Sketch3" profile of A4 L11 L12 A3 along normal blind 18
extrude "Extrude12" new body sketch "Sketch3" profile of L1 L3 A1 A2 A4 L11 L12 A3 against normal blind 15 bodies "top"
extrude "Extrude13" cut sketch "Sketch3" profile of A4 L11 L12 A3 against normal blind 13
work_axis "WorkAxis1"
work_plane "WorkPlane1" RotateAngle 0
